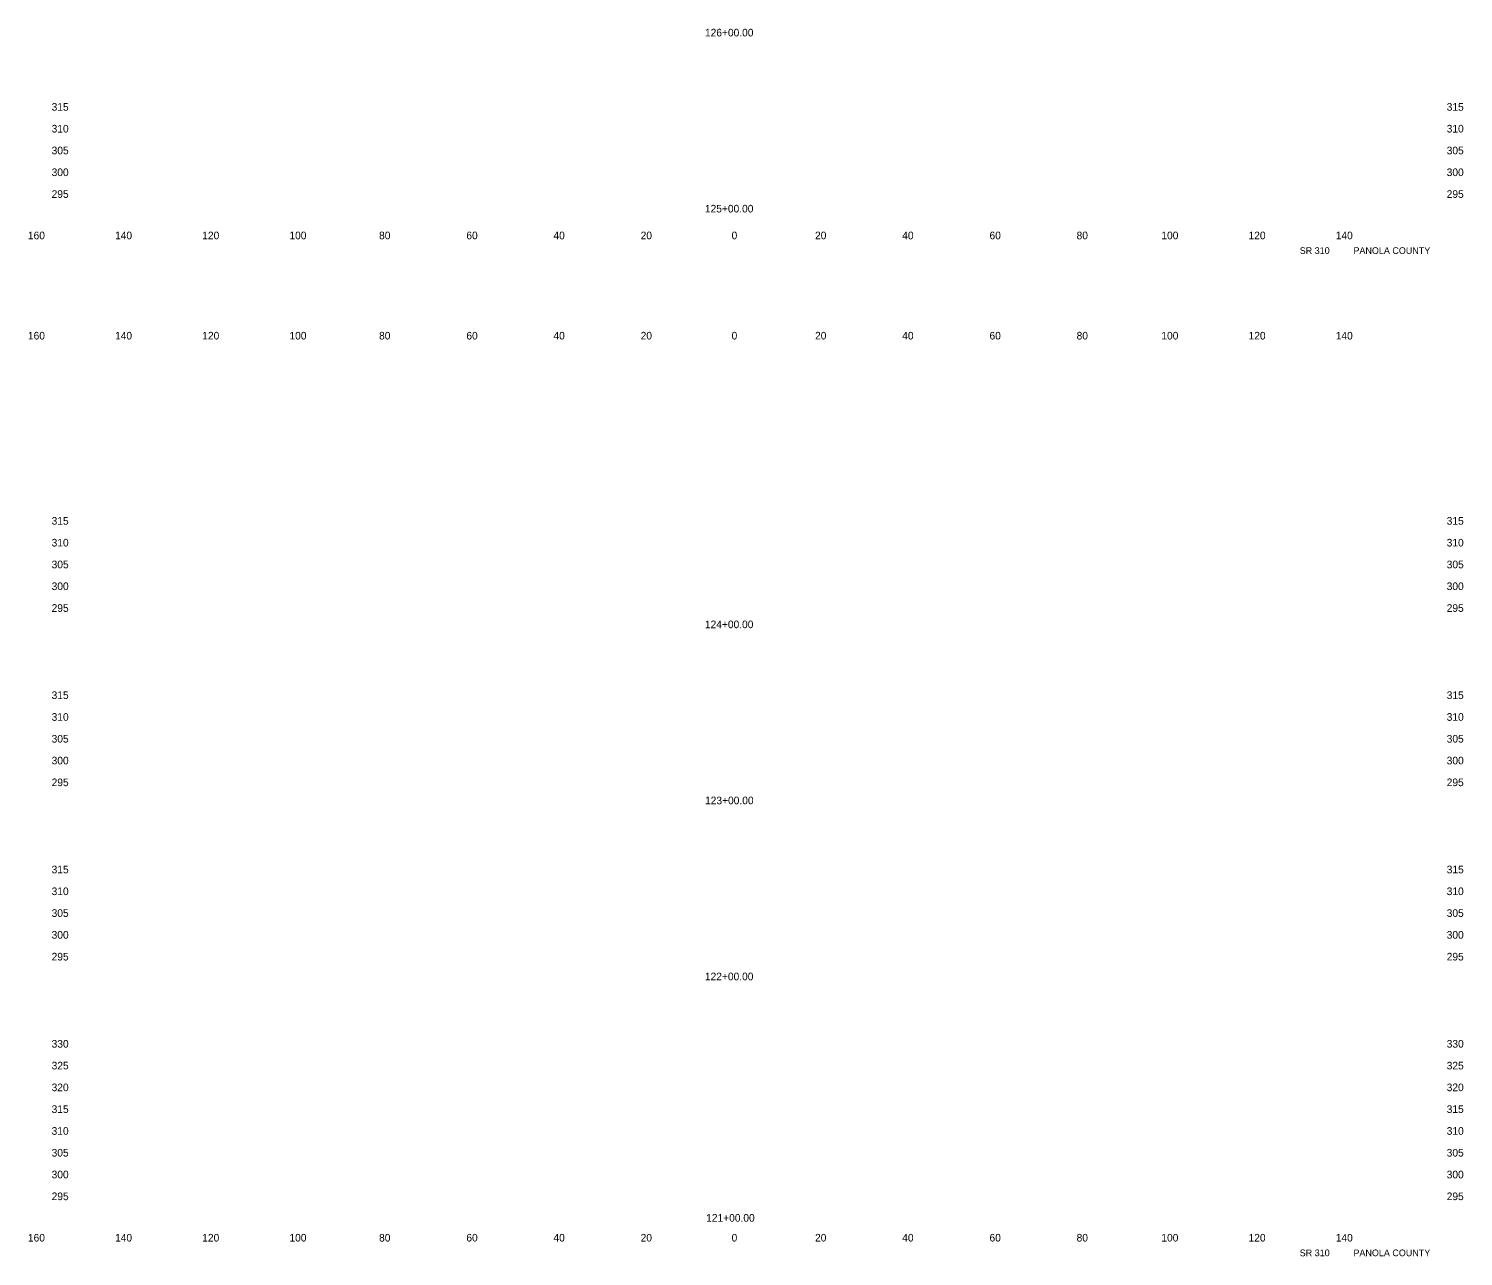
# Model space of a CAD drawing. Extents: x 21481 to 21810, y 6485 to 11067.
# Drawn here: x 21480.9 to 21809.9, y 8784.8 to 9066.5 of the extents above; entities that cross this region are included whole.
import ezdxf

# ---------------------------------------------------------------- set-up
doc = ezdxf.new("R2010")
doc.units = 0
for name, color, linetype in [('62', 7, 'Continuous'), ('XS_CELL', 7, 'Continuous'), ('XS_P_TX_DCH', 7, 'Continuous'), ('XS_P_TX_FS_BS', 7, 'Continuous')]:
    doc.layers.add(name, color=color, linetype=linetype)

msp = doc.modelspace()

# ---------------------------------------------------------------- texts
at = {"layer": '62'}
for s, p in [('  160  ', (21479.4, 9018.21)), ('  140  ', (21499.39, 9018.21)), ('  120  ', (21519.39, 9018.21)), ('  100  ', (21539.39, 9018.21)), ('  80  ', (21559.95, 9018.21)), ('  60  ', (21579.97, 9018.21)), ('  40  ', (21599.95, 9018.21)), ('  20  ', (21619.95, 9018.21)), ('  0  ', (21640.81, 9018.21)), ('  0  ', (21640.81, 9018.21)), ('  20  ', (21659.95, 9018.21)), ('  40  ', (21679.95, 9018.21)), ('  60  ', (21699.97, 9018.21)), ('  80  ', (21719.95, 9018.21)), ('  100  ', (21739.39, 9018.21)), ('  120  ', (21759.39, 9018.21)), ('  140  ', (21779.39, 9018.21)), ('  160  ', (21479.4, 8995.21)), ('  140  ', (21499.39, 8995.21)), ('  120  ', (21519.39, 8995.21)), ('  100  ', (21539.39, 8995.21)), ('  80  ', (21559.95, 8995.21)), ('  60  ', (21579.97, 8995.21)), ('  40  ', (21599.95, 8995.21)), ('  20  ', (21619.95, 8995.21)), ('  0  ', (21640.81, 8995.21)), ('  0  ', (21640.81, 8995.21)), ('  20  ', (21659.95, 8995.21)), ('  40  ', (21679.95, 8995.21)), ('  60  ', (21699.97, 8995.21)), ('  80  ', (21719.95, 8995.21)), ('  100  ', (21739.39, 8995.21)), ('  120  ', (21759.39, 8995.21)), ('  140  ', (21779.39, 8995.21)), ('  160  ', (21479.4, 8788.21)), ('  140  ', (21499.39, 8788.21)), ('  120  ', (21519.39, 8788.21)), ('  100  ', (21539.39, 8788.21)), ('  80  ', (21559.95, 8788.21)), ('  60  ', (21579.97, 8788.21)), ('  40  ', (21599.95, 8788.21)), ('  20  ', (21619.95, 8788.21)), ('  0  ', (21640.81, 8788.21)), ('  0  ', (21640.81, 8788.21)), ('  20  ', (21659.95, 8788.21)), ('  40  ', (21679.95, 8788.21)), ('  60  ', (21699.97, 8788.21)), ('  80  ', (21719.95, 8788.21)), ('  100  ', (21739.39, 8788.21)), ('  120  ', (21759.39, 8788.21)), ('  140  ', (21779.39, 8788.21))]:
    msp.add_text(s, height=1.75, dxfattribs=at).set_placement(p)
at = {"layer": 'XS_CELL'}
for s, p in [('  315  ', (21484.84, 9047.71)), ('  315  ', (21804.84, 9047.71)), ('  310  ', (21484.84, 9042.71)), ('  310  ', (21804.84, 9042.71)), ('  305  ', (21484.84, 9037.71)), ('  305  ', (21804.84, 9037.71)), ('  300  ', (21484.84, 9032.71)), ('  300  ', (21804.84, 9032.71)), ('  295  ', (21484.84, 9027.71)), ('  295  ', (21804.84, 9027.71)), ('  315  ', (21484.84, 8952.71)), ('  315  ', (21804.84, 8952.71)), ('  310  ', (21484.84, 8947.71)), ('  310  ', (21804.84, 8947.71)), ('  305  ', (21484.84, 8942.71)), ('  305  ', (21804.84, 8942.71)), ('  300  ', (21484.84, 8937.71)), ('  300  ', (21804.84, 8937.71)), ('  295  ', (21484.84, 8932.71)), ('  295  ', (21804.84, 8932.71)), ('  315  ', (21484.84, 8912.71)), ('  315  ', (21804.84, 8912.71)), ('  310  ', (21484.84, 8907.71)), ('  310  ', (21804.84, 8907.71)), ('  305  ', (21484.84, 8902.71)), ('  305  ', (21804.84, 8902.71)), ('  300  ', (21484.84, 8897.71)), ('  300  ', (21804.84, 8897.71)), ('  295  ', (21484.84, 8892.71)), ('  295  ', (21804.84, 8892.71)), ('  315  ', (21484.84, 8872.71)), ('  315  ', (21804.84, 8872.71)), ('  310  ', (21484.84, 8867.71)), ('  310  ', (21804.84, 8867.71)), ('  305  ', (21484.84, 8862.71)), ('  305  ', (21804.84, 8862.71)), ('  300  ', (21484.84, 8857.71)), ('  300  ', (21804.84, 8857.71)), ('  295  ', (21484.84, 8852.71)), ('  295  ', (21804.84, 8852.71)), ('  330  ', (21484.84, 8832.71)), ('  330  ', (21804.84, 8832.71)), ('  325  ', (21484.84, 8827.71)), ('  325  ', (21804.84, 8827.71)), ('  320  ', (21484.84, 8822.71)), ('  320  ', (21804.84, 8822.71)), ('  315  ', (21484.84, 8817.71)), ('  315  ', (21804.84, 8817.71)), ('  310  ', (21484.84, 8812.71)), ('  310  ', (21804.84, 8812.71)), ('  305  ', (21484.84, 8807.71)), ('  305  ', (21804.84, 8807.71)), ('  300  ', (21484.84, 8802.71)), ('  300  ', (21804.84, 8802.71)), ('  295  ', (21484.84, 8797.71)), ('  295  ', (21804.84, 8797.71))]:
    msp.add_text(s, height=1.75, dxfattribs=at).set_placement(p)
at = {"layer": 'XS_P_TX_DCH'}
for s, p in [('  126+00.00  ', (21634.7, 9064.76)), ('  125+00.00  ', (21634.69, 9024.36)), ('  124+00.00  ', (21634.69, 8928.96)), ('  123+00.00  ', (21634.72, 8888.56)), ('  122+00.00  ', (21634.69, 8848.16)), ('  121+00.00  ', (21634.98, 8792.76))]:
    msp.add_text(s, height=1.75, dxfattribs=at).set_placement(p)
at = {"layer": 'XS_P_TX_FS_BS'}
for s, p in [('SR 310', (21772.43, 9014.84)), ('SR 310', (21772.43, 9014.84)), ('SR 310', (21772.43, 9014.84)), ('PANOLA COUNTY', (21784.75, 9014.84)), ('PANOLA COUNTY', (21784.75, 9014.84)), ('PANOLA COUNTY', (21784.75, 9014.84)), ('SR 310', (21772.43, 8784.84)), ('SR 310', (21772.43, 8784.84)), ('SR 310', (21772.43, 8784.84)), ('PANOLA COUNTY', (21784.75, 8784.84)), ('PANOLA COUNTY', (21784.75, 8784.84)), ('PANOLA COUNTY', (21784.75, 8784.84))]:
    msp.add_text(s, height=1.54, dxfattribs=at).set_placement(p)

doc.saveas('drawing.dxf')
